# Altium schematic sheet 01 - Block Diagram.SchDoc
size B; CompanyName: Microchip Technology Inc.; Organization: Microchip Technology; Address1: 2355 West Chandler Blvd.; Address2: Chandler, AZ  85224; Address4: USA; DocumentNumber: 1; SheetNumber: 1; SheetTotal: 13; SheetTitle: Block Diagram
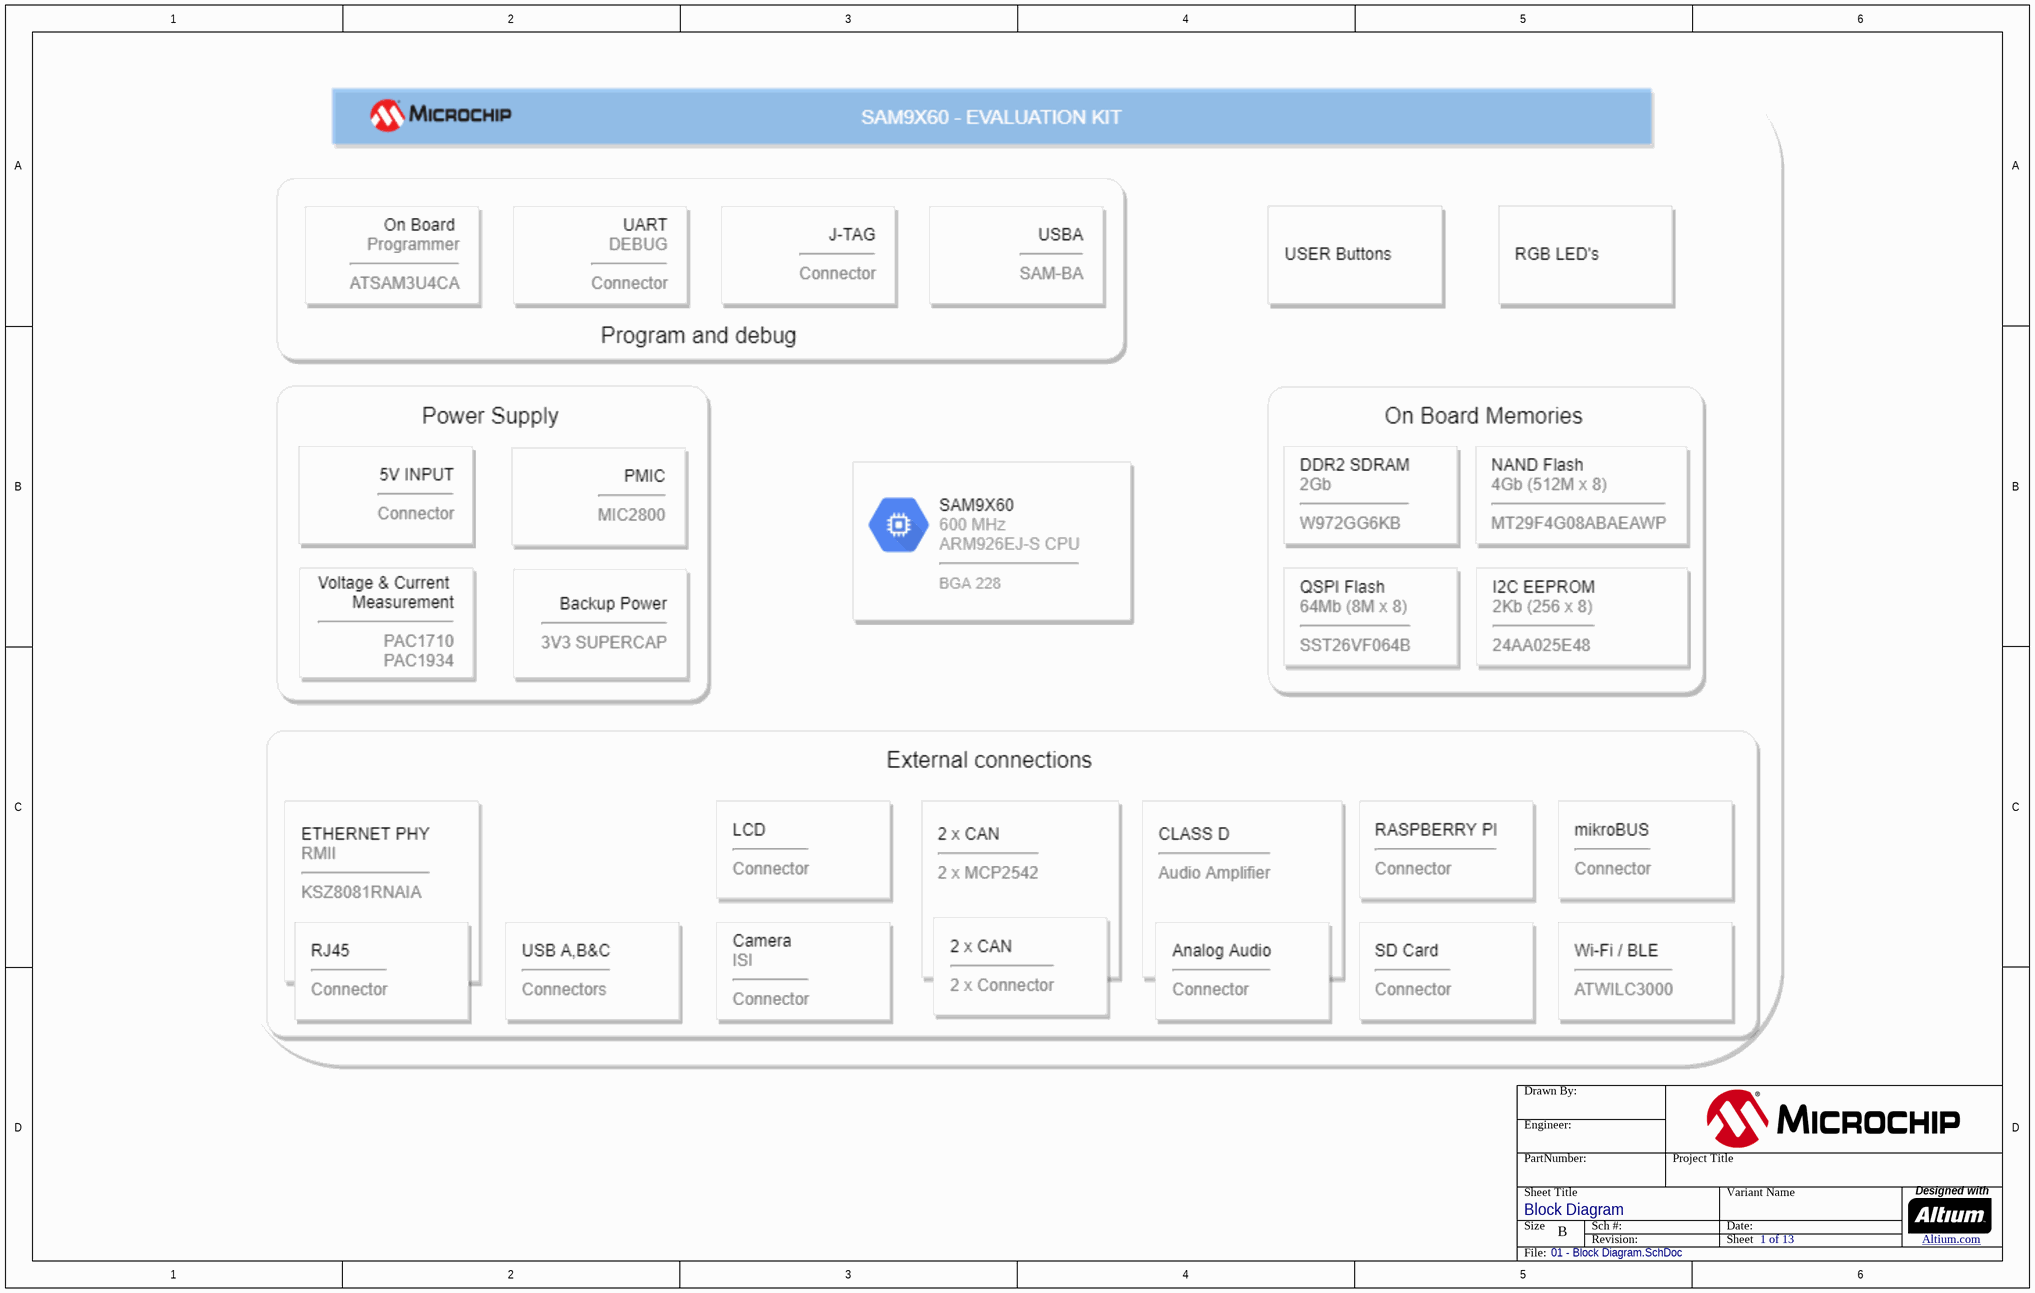
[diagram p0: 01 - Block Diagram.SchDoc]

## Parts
?  (no value)  (graphical)

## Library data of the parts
? = Title Block B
